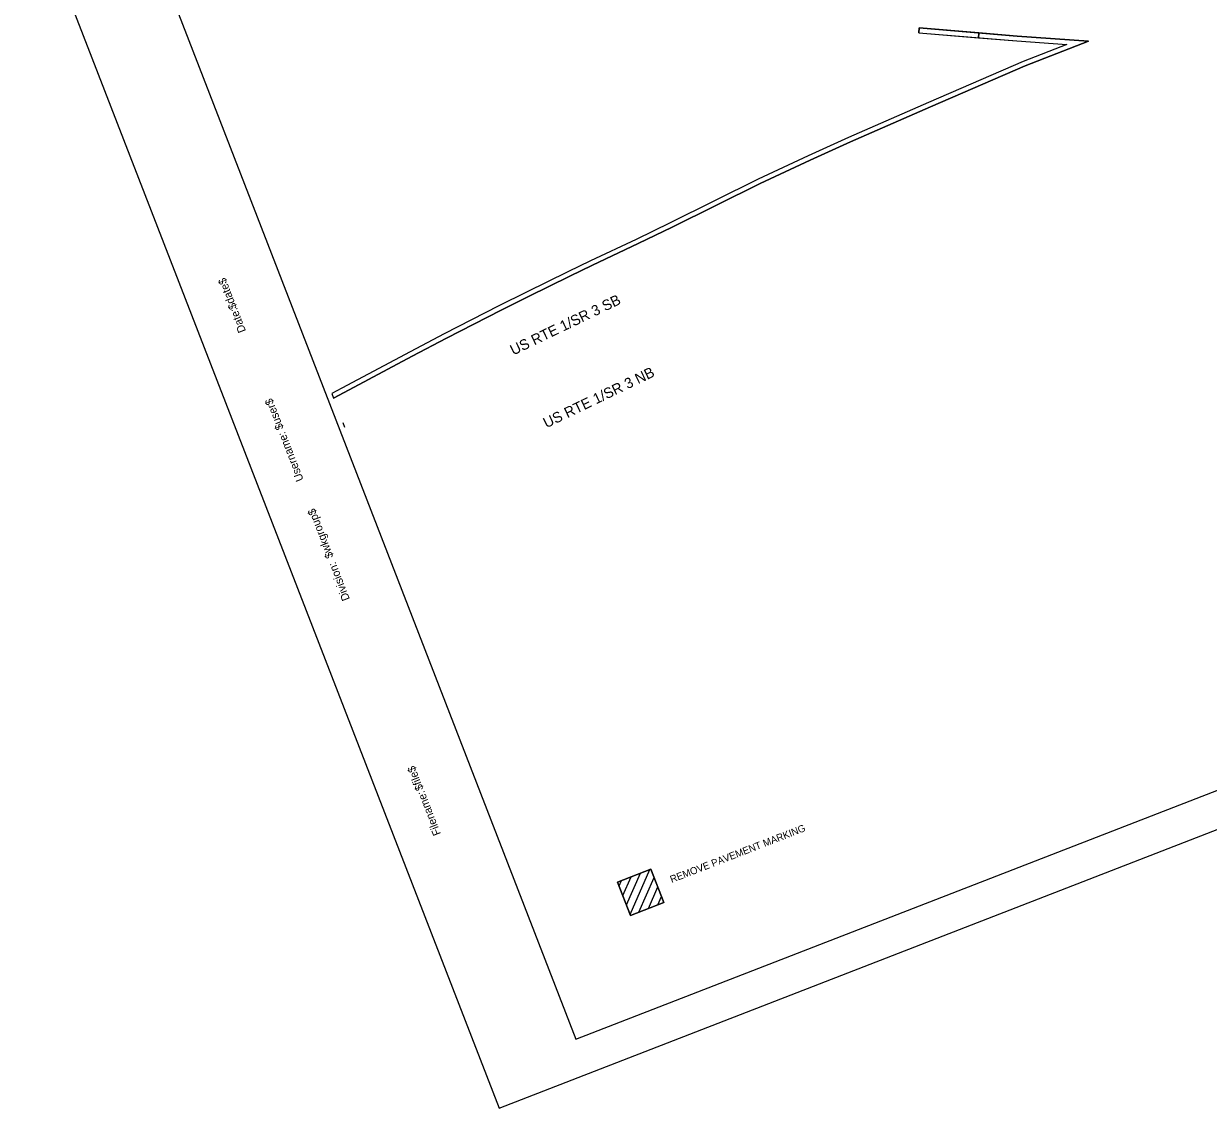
# Model space of a CAD drawing. Extents: x 1668445 to 1669436, y 339301 to 340121.
# Drawn here: x 1668444.9 to 1668940.6, y 339301.1 to 339754.7 of the extents above; entities that cross this region are included whole.
import ezdxf

# ---------------------------------------------------------------- set-up
doc = ezdxf.new("R2010")
doc.units = 0
for name, color, linetype in [('ANNOTATION', 7, 'Continuous'), ('BORDER', 7, 'Continuous'), ('PATTERNING', 7, 'Continuous'), ('PLOT BOUNDARY', 7, 'Continuous'), ('SHADING', 7, 'Continuous')]:
    doc.layers.add(name, color=color, linetype=linetype)

msp = doc.modelspace()

# ---------------------------------------------------------------- linework, layer by layer
at = {"layer": 'BORDER'}
for p, q in [((1668486.16, 339819.44), (1668676.03, 339329.98)), ((1668676.03, 339329.98), (1669421.88, 339619.29))]:
    msp.add_line(p, q, dxfattribs=at)
at = {"layer": 'PATTERNING'}
for p, q in [((1668819.48, 339750.93), (1668819.62, 339752.93)), ((1668819.62, 339752.93), (1668819.48, 339750.93)), ((1668819.48, 339750.93), (1668844.5, 339748.83)), ((1668844.65, 339750.83), (1668819.62, 339752.93)), ((1668844.64, 339750.7), (1668844.5, 339748.83)), ((1668844.5, 339748.83), (1668844.64, 339750.7)), ((1668844.5, 339748.83), (1668860.49, 339747.49)), ((1668573.8, 339599.98), (1668574.53, 339598.1)), ((1668573.8, 339599.98), (1668574.53, 339598.1)), ((1668578.5, 339587.84), (1668579.23, 339585.96)), ((1668695.61, 339390.1), (1668699.05, 339397.9)), ((1668697.14, 339386.14), (1668703.01, 339399.44)), ((1668698.68, 339382.19), (1668706.96, 339400.97)), ((1668702.36, 339383.1), (1668708.77, 339397.64)), ((1668694.08, 339394.06), (1668695.1, 339396.37)), ((1668706.31, 339384.63), (1668710.31, 339393.69)), ((1668710.27, 339386.16), (1668711.84, 339389.73))]:
    msp.add_line(p, q, dxfattribs=at)
for points in [[(1668819.48, 339750.93), (1668860.49, 339747.49), (1668881.46, 339746.06), (1668863.17, 339738.87), (1668823.52, 339721.76), (1668801.19, 339712.03), (1668790.05, 339707.1), (1668773.2, 339699.47), (1668764.81, 339695.58), (1668752.28, 339689.61), (1668715.46, 339671.37), (1668701.21, 339664.51), (1668682.14, 339655.46), (1668672.62, 339650.91), (1668655.29, 339642.42), (1668643.79, 339636.66), (1668620.91, 339624.92), (1668606.6, 339617.43), (1668578.07, 339602.28), (1668573.8, 339599.98)], [(1668819.62, 339752.93), (1668860.64, 339749.48), (1668890.46, 339747.46), (1668863.93, 339737.02), (1668824.32, 339719.92), (1668802, 339710.2), (1668790.87, 339705.27), (1668774.04, 339697.66), (1668765.66, 339693.77), (1668753.15, 339687.81), (1668716.34, 339669.57), (1668702.07, 339662.7), (1668683, 339653.66), (1668673.49, 339649.11), (1668656.18, 339640.63), (1668644.7, 339634.87), (1668621.83, 339623.14), (1668607.53, 339615.66), (1668579.02, 339600.52), (1668574.53, 339598.1)], [(1668574.53, 339598.1), (1668579.02, 339600.52), (1668607.53, 339615.66), (1668621.83, 339623.14), (1668644.7, 339634.87), (1668656.18, 339640.63), (1668673.49, 339649.11), (1668683, 339653.66), (1668702.07, 339662.7), (1668716.34, 339669.57), (1668753.15, 339687.81), (1668765.66, 339693.77), (1668774.04, 339697.66), (1668790.87, 339705.27), (1668802, 339710.2), (1668824.32, 339719.92), (1668863.93, 339737.02), (1668890.46, 339747.46), (1668860.64, 339749.48), (1668844.65, 339750.83)], [(1668844.65, 339750.83), (1668844.64, 339750.7)], [(1668844.64, 339750.7), (1668844.65, 339750.83)], [(1668860.49, 339747.49), (1668881.46, 339746.06), (1668863.17, 339738.87), (1668823.52, 339721.76), (1668801.19, 339712.03), (1668790.05, 339707.1), (1668773.2, 339699.47), (1668764.81, 339695.58), (1668752.28, 339689.61), (1668715.46, 339671.37), (1668701.21, 339664.51), (1668682.14, 339655.46), (1668672.62, 339650.91), (1668655.29, 339642.42), (1668643.79, 339636.66), (1668620.91, 339624.92), (1668606.6, 339617.43), (1668578.07, 339602.28), (1668573.8, 339599.98)]]:
    msp.add_lwpolyline(points, dxfattribs=at)
msp.add_lwpolyline([(1668693.43, 339395.72), (1668707.41, 339401.15), (1668712.84, 339387.16), (1668698.85, 339381.74)], close=True, dxfattribs=at)
at = {"layer": 'PLOT BOUNDARY'}
msp.add_lwpolyline([(1668643.83, 339301.08), (1669436.3, 339608.48), (1669237.39, 340121.26), (1668444.93, 339813.86)], close=True, dxfattribs=at)
at = {"layer": 'SHADING'}
for p, q in [((1668819.62, 339752.93), (1668819.48, 339750.93)), ((1668819.48, 339750.93), (1668844.5, 339748.83)), ((1668844.65, 339750.83), (1668819.62, 339752.93)), ((1668844.64, 339750.7), (1668844.5, 339748.83)), ((1668844.5, 339748.83), (1668844.64, 339750.7)), ((1668844.5, 339748.83), (1668860.49, 339747.49)), ((1668844.65, 339750.83), (1668844.64, 339750.7)), ((1668844.64, 339750.7), (1668844.65, 339750.83)), ((1668573.8, 339599.98), (1668574.53, 339598.1))]:
    msp.add_line(p, q, dxfattribs=at)
for points in [[(1668574.53, 339598.1), (1668579.02, 339600.52), (1668607.53, 339615.66), (1668621.83, 339623.14), (1668644.7, 339634.87), (1668656.18, 339640.63), (1668673.49, 339649.11), (1668683, 339653.66), (1668702.07, 339662.7), (1668716.34, 339669.57), (1668753.15, 339687.81), (1668765.66, 339693.77), (1668774.04, 339697.66), (1668790.87, 339705.27), (1668802, 339710.2), (1668824.32, 339719.92), (1668863.93, 339737.02), (1668890.46, 339747.46), (1668860.64, 339749.48), (1668844.65, 339750.83)], [(1668860.49, 339747.49), (1668881.46, 339746.06), (1668863.17, 339738.87), (1668823.52, 339721.76), (1668801.19, 339712.03), (1668790.05, 339707.1), (1668773.2, 339699.47), (1668764.81, 339695.58), (1668752.28, 339689.61), (1668715.46, 339671.37), (1668701.21, 339664.51), (1668682.14, 339655.46), (1668672.62, 339650.91), (1668655.29, 339642.42), (1668643.79, 339636.66), (1668620.91, 339624.92), (1668606.6, 339617.43), (1668578.07, 339602.28), (1668573.8, 339599.98)], [(1668698.85, 339381.74), (1668712.84, 339387.16), (1668707.41, 339401.15), (1668693.43, 339395.72), (1668698.85, 339381.74)]]:
    msp.add_lwpolyline(points, dxfattribs=at)

# ---------------------------------------------------------------- texts
at = {"layer": 'ANNOTATION'}
for s, height, rotation, p in [('US RTE 1/SR 3 SB', 4.375, 25.6533, (1668649.79, 339615.9)), ('US RTE 1/SR 3 NB', 4.375, 25.6533, (1668663.62, 339585.47)), ('REMOVE PAVEMENT MARKING', 3, 21.2013, (1668716.08, 339395.3))]:
    msp.add_text(s, height=height, rotation=rotation, dxfattribs=at).set_placement(p)
at = {"layer": 'BORDER'}
for s, p in [('$date$', (1668534.21, 339635.92)), ('Date:', (1668537.99, 339626.19)), ('$user$', (1668553.76, 339585.52)), ('Username:', (1668562.12, 339563.96)), ('$wkgroup$', (1668574.6, 339531.8)), ('Division:', (1668581.47, 339514.07)), ('$file$', (1668612.29, 339434.64)), ('Filename:', (1668619.57, 339415.87))]:
    msp.add_text(s, height=3.348, rotation=111.2013, dxfattribs=at).set_placement(p)

doc.saveas('drawing.dxf')
